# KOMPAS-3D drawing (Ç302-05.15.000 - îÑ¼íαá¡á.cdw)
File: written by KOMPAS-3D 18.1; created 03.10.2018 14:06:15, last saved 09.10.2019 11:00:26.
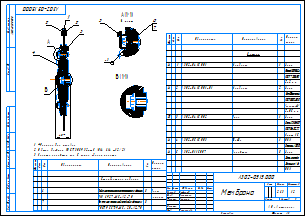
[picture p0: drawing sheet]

Sheet 1: A3, landscape

Document properties: Автор: Милов; Полное имя файла: D:\Мембранные насосы\Мембранный электропривод\А302-00.00.000 - ASTRA-302 (МЭ200)\А302-05.00.000 - Мембранный насос ASTRA-302-PVC\А302-05.15.000 - Мембрана.cdw; Масса: 2.62614

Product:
- Part/product: (unnamed)
  - Component: Болт с шестигранной головкой с фланцем  / ГОСТ Р 55739-М5 x 20-A2-70  | pos. 7  | Раздел спецификации: Стандартные изделия
  - Component: Гайка шестигранная самостопорящаяся с фланцем / DIN 6927-M5-A2-70  | pos. 6  | Раздел спецификации: Стандартные изделия; Примечание: Нерж. / насечки
  - Component: Заглушка  | designation А302-01.15.007  | pos. 5  | Раздел спецификации: Детали; Форматы листов документа: А4; Примечание: Заим. / Деталь заготовка  / Заглушка @2~16 / ПВХ
  - Component: Шайба  | designation А302-05.15.003  | pos. 4  | Раздел спецификации: Детали; Форматы листов документа: А4; Примечание: ПВХ / Стержень @2~300
  - Component: Упор  | designation А302-04.15.002  | pos. 3  | Раздел спецификации: Детали; Форматы листов документа: А3; Примечание: Заим. / Сталь 12Х18Н10Т / ГОСТ 5632-72 / Лист 15
  - Component: Мембрана  | designation А302-04.15.001-01  | pos. 2  | Раздел спецификации: Детали; Форматы листов документа: А4; Примечание: Заим. / Лист Фторопласт-4 /  ГОСТ 10007-80 Е / "каленный" / S=0,5 мм
  - Component: Мембрана  | designation А302-04.15.001  | pos. 1  | Раздел спецификации: Детали; Форматы листов документа: А4; Примечание: Заим. / Пластина ІФ-IІ ТМКЩ-C-4 / ГОСТ 7338-90 / S=2 мм

Title block, sheet 1: Наименование: Мембрана; designation: А302-05.15.000; Масса: 2,63; scale: 1:2; Количество листов документа: 1; organisation: АО «Астерион»; Форматы листов документа: A3; stored path: \\192.168.87.28\Konstructor_doc\Мембранные насосы\Мембранный электропривод\А302-00.00.000 - ASTRA-302 (МЭ200)\3Д ПВХ\А302-01.15.000 - Мембрана.cdw; Разработал: Лифлянд; Проверил: Борисенко; Т. контр.: Лучихин; Утвердил: Григорьева

Views: Вид 1, Местный разрез 1, Вид:2, Выносной элемент 3, Выносной элемент А, Выносной элемент, Выносной элемент Б
Referenced files in D:\Мембранные насосы\Мембранный электропривод\А302-00.00.000 - ASTRA-302 (МЭ200)\3Д ПВХ\: А302-01.15.001-01- Мембрана.m3d, А302-01.15.007 - Заглушка.m3d, А302-01.15.001 - Мембрана.m3d, А302-01.15.002 - Упор.a3d, А302-01.15.003 - Шайба.m3d, А302-01.15.000 - Мембрана.a3d, А302-01.15.001 - Мембрана.cdw, А302-01.15.002 - Упор.m3d, А302-01.15.008 - Кольцо плоское Ф4.m3d, А302-01.15.008 - Кольцо плоское уплотнительное 5-13-10 Ф4.cdw, А302-01.15.009 - Кольцо плоское Ф4.m3d, А302-01.15.007 - Заглушка.cdw, А302-01.15.011 - Заглушка резьбовая.m3d, А302-01.15.011 - Заглушка резьбовая.cdw
Referenced files in Z:\Мембранные насосы\Мембранный электропривод\А302-00.00.000 - ASTRA-302 (МЭ200)\3Д ПВХ\: А302-01.15.000 - Мембрана.a3d, А302-01.15.008 - Кольцо плоское Ф4.m3d
Referenced files in D:\2 Стандартные изделия 3D\Гайки\DIN 6927\: Гайка шестигранная самостопорящаяся с фланцем DIN 6927-M5 - A2-70.m3d
Referenced files in \\192.168.87.28\Konstructor_doc\Мембранные насосы\Мембранный электропривод\А302-00.00.000 - ASTRA-302 (МЭ200)\3Д ПВХ\: А302-01.15.011 - Заглушка резьбовая.cdw
Referenced files in D:\Мембранные насосы\Мембранный электропривод\А302-00.00.000 - ASTRA-302 (МЭ200)\А302-05.00.000 - Мембранный насос ASTRA-302-PVC\: А302-02.15.002 - Упор.cdw
Referenced files in C:\Program Files\ASCON\KOMPAS-3D v18\Libs\PartLib\DATA\VAULT\methods\kompas\3d\: PLib_Bolt_1_ISO_1100.m3d, PLib_Nut_ISO_1100.m3d
Referenced files in C:\Program Files\ASCON\KOMPAS-3D V16\Libs\PartLib\DATA\vault\Methods\Kompas\3D\: PLib_Nut_ISO_1100.m3d, PLib_Bolt_1_ISO_1100.m3d
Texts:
  Шайба
  Упор
  Болт с шестигранной головкой с фланцем
  ГОСТ Р  55739-М5 x 25-A2-70
  ГОСТ
  Нерж.
  Нержавеющая сталь
  Гайка шестигранная самостопорящаяся с фланцем
  DIN 6927-M5-A2-70
  Гайка
  шестигранная
  самостопорящаяся
  фланцем
  DIN
  насечки
  Нерж. / насечки
  Кольцо плоское
  уплотнительное 5-13-10 Ф4
  Кольцо плоское  / уплотнительное 5-13-10 Ф4
  ГОСТ Р  55739-М8 x 30-A2-70
  Кольцо плоское Ф4
  Заглушка
  Заглушка резьбовая
  Лента ФУМ
  Лента
  ФУМ
  3D_Doc-graphic.lyt,1.000000-4294967295-203648116615
  Болт с шестигранной головкой с фланцем ГОСТ Р 55739-М5 x 20-A2-70
  Болт
  шестигранной
  головкой
  Заим.
  Пластина ІФ-IІ ТМКЩ-C-4
  ГОСТ 7338-90
  Заим. / Пластина ІФ-IІ ТМКЩ-C-4 / ГОСТ 7338-90 / S=2 мм
  Лист Фторопласт-4
  ГОСТ 10007-80 Е
  "каленный"
  Заим. / Лист Фторопласт-4 /  ГОСТ 10007-80 Е / "каленный" / S=0,5 мм
  Сталь 12Х18Н10Т
  ГОСТ 5632-72
  Лист 15
  Заим. / Сталь 12Х18Н10Т / ГОСТ 5632-72 / Лист 15
  ПВХ
  Стержень  300
  ПВХ / Стержень @2~300
  Деталь заготовка
  Заглушка  16
  Заим. / Деталь заготовка  / Заглушка @2~16 / ПВХ
  ГОСТ Р 55739-М5 x 20-A2-70
  Болт с шестигранной головкой с фланцем ГОСТ Р 55739-М5 x 25-A2-70
  Гайка шестигранная с фланцем ГОСТ Р ИСО 4161 - M5 - A2-70
  Гайка шестигранная самостопорящаяся с фланцем / DIN 6927-M5-A2-70
  Болт с шестигранной головкой с фланцем ГОСТ Р 55739-М8 x 16-A2-70
Dimensions and other numbers on the sheet: 2; 1; 3; 4; 40; 8 мест; 5; 6; 7; 10; 9; 11; 8; 12; 100; 41; 48; 1:2; 2,63

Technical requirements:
  *Размеры для справок.
  Общие допуски ГОСТ 30893.2-mK (H14, h14,  t2/2).
  Клеить заглушки поз. 5 после сборки пакета.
